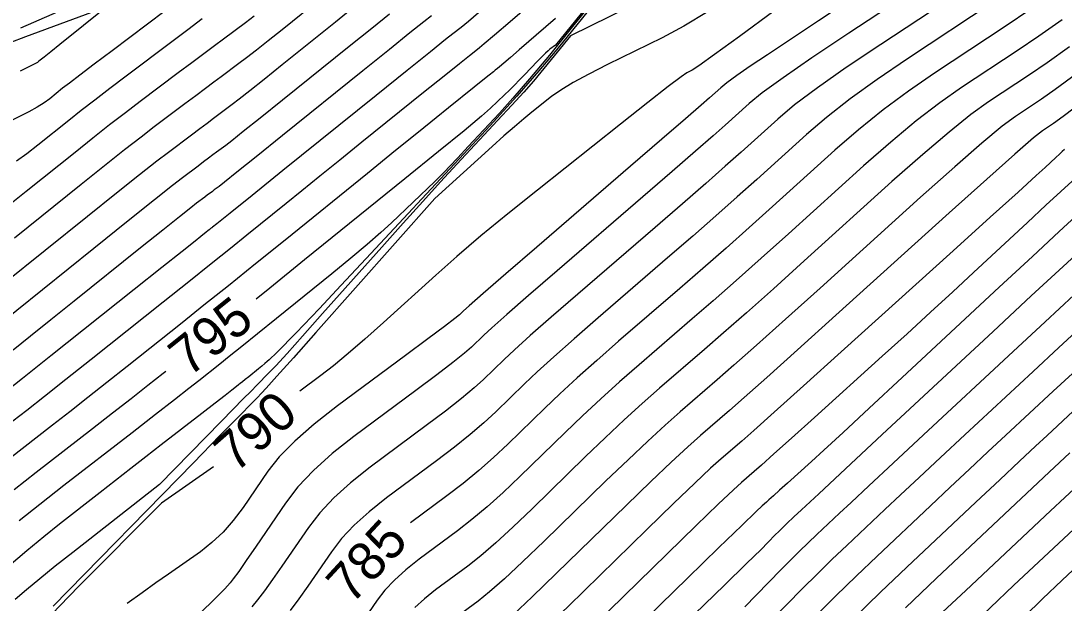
# Model space of a CAD drawing. Extents: x 2079879 to 2092887, y 778083 to 784051.
# Drawn here: x 2084359.8 to 2084435.7, y 781096.1 to 781138.5 of the extents above; entities that cross this region are included whole.
import ezdxf

# ---------------------------------------------------------------- set-up
doc = ezdxf.new("R2010")
doc.units = 0
doc.layers.add('DT_X_Contour_Major', color=7, linetype='Continuous')
doc.layers.add('DT_X_Contour_Minor', color=7, linetype='Continuous')

msp = doc.modelspace()

# ---------------------------------------------------------------- linework, layer by layer
at = {"layer": 'DT_X_Contour_Major'}
for points in [[(2084407.524, 781147.596), (2084398.692, 781136.684), (2084398.271, 781136.383), (2084398.148, 781136.28), (2084397.959, 781136.1), (2084397.704, 781135.844), (2084397.383, 781135.512), (2084396.439, 781134.523), (2084396.082, 781134.153), (2084395.72, 781133.787), (2084395.352, 781133.424), (2084394.978, 781133.065), (2084393.973, 781132.109), (2084393.302, 781131.519), (2084392.04, 781130.466), (2084390.188, 781128.948), (2084387.747, 781126.968), (2084380.449, 781121.068), (2084377.926, 781119.029), (2084376.92, 781118.218)], [(2084370.308, 781139.179), (2084366.451, 781136.283), (2084365.142, 781135.298), (2084364.106, 781134.513), (2084363.344, 781133.93), (2084362.856, 781133.547), (2084361.919, 781132.794), (2084361.515, 781132.5), (2084361.008, 781132.184), (2084360.396, 781131.844), (2084359.681, 781131.482), (2084357.634, 781130.485), (2084356.741, 781129.967), (2084355.597, 781129.161), (2084354.202, 781128.067), (2084353.247, 781127.265)], [(2084386.613, 781138.939), (2084385.327, 781137.907), (2084383.687, 781136.588), (2084378.841, 781132.687), (2084377.22, 781131.383), (2084375.991, 781130.4), (2084375.155, 781129.736), (2084374.711, 781129.393), (2084374.051, 781128.902), (2084373.781, 781128.702), (2084373.467, 781128.467), (2084373.108, 781128.198), (2084372.704, 781127.895), (2084371.568, 781127.042), (2084370.845, 781126.481), (2084369.528, 781125.437), (2084367.618, 781123.91), (2084365.113, 781121.901), (2084357.641, 781115.898), (2084355.184, 781113.926), (2084353.573, 781112.636)], [(2084414.557, 781139.145), (2084412.07, 781137.326), (2084410.253, 781136.007), (2084409.104, 781135.186), (2084408.623, 781134.865), (2084408.233, 781134.673), (2084407.822, 781134.386), (2084406.881, 781133.668), (2084405.412, 781132.519), (2084403.413, 781130.94), (2084397.377, 781126.153), (2084395.218, 781124.421), (2084393.267, 781122.814), (2084391.526, 781121.331), (2084389.993, 781119.974), (2084386.184, 781116.521), (2084384.828, 781115.308), (2084383.614, 781114.261), (2084382.544, 781113.379), (2084381.618, 781112.661), (2084380.099, 781111.534)], [(2084433.261, 781139.295), (2084431.394, 781138.043), (2084426.258, 781134.651), (2084424.36, 781133.346), (2084422.52, 781131.976), (2084420.736, 781130.541), (2084419.01, 781129.04), (2084414.481, 781124.952), (2084412.786, 781123.43), (2084411.098, 781121.931), (2084409.416, 781120.455), (2084407.741, 781119.002), (2084403.283, 781115.158), (2084401.694, 781113.773), (2084400.27, 781112.503), (2084399.012, 781111.347), (2084397.919, 781110.304), (2084395.225, 781107.677), (2084394.191, 781106.704), (2084393.109, 781105.753), (2084391.979, 781104.827), (2084390.802, 781103.923), (2084388.157, 781101.959)], [(2084435.706, 781129.108), (2084435.542, 781128.957), (2084435.328, 781128.758), (2084435.062, 781128.512), (2084434.287, 781127.79), (2084433.651, 781127.209), (2084432.325, 781126.006), (2084430.308, 781124.183), (2084427.601, 781121.738), (2084419.463, 781114.39), (2084416.722, 781111.918), (2084414.603, 781110.014), (2084413.106, 781108.677), (2084412.232, 781107.908), (2084410.729, 781106.612), (2084409.969, 781105.926), (2084408.815, 781104.841), (2084407.268, 781103.356), (2084405.328, 781101.471), (2084399.628, 781095.913), (2084397.709, 781094.054), (2084396.816, 781093.203)], [(2084437.141, 781116.411), (2084435.28, 781114.697), (2084433.417, 781112.97), (2084428.449, 781108.346), (2084426.689, 781106.707), (2084425.134, 781105.256), (2084423.786, 781103.995), (2084422.643, 781102.922), (2084419.871, 781100.315), (2084418.818, 781099.313), (2084417.74, 781098.263), (2084416.636, 781097.164), (2084415.505, 781096.018), (2084412.457, 781092.896), (2084411.278, 781091.698), (2084410.029, 781090.445), (2084408.709, 781089.138), (2084407.317, 781087.777), (2084406.034, 781086.527)], [(2084370.36, 781112.971), (2084370.154, 781112.806), (2084369.058, 781111.938), (2084367.837, 781110.979), (2084366.491, 781109.928), (2084365.019, 781108.786), (2084360.929, 781105.619), (2084359.33, 781104.356)], [(2084373.825, 781106.031), (2084370.044, 781103.39), (2084364.036, 781097.358), (2084362.64, 781095.93), (2084361.029, 781094.228), (2084359.201, 781092.254)], [(2084437.075, 781102.155), (2084432.031, 781097.423), (2084430.302, 781095.791), (2084428.898, 781094.448), (2084427.82, 781093.391), (2084427.067, 781092.622), (2084425.493, 781090.954), (2084424.917, 781090.353), (2084424.371, 781089.801), (2084423.854, 781089.298), (2084423.366, 781088.845), (2084422.105, 781087.701), (2084421.464, 781087.091), (2084420.486, 781086.119), (2084419.172, 781084.785), (2084417.521, 781083.09), (2084415.383, 781080.885)]]:
    msp.add_lwpolyline(points, dxfattribs=at)
at = {"layer": 'DT_X_Contour_Minor'}
for points in [[(2084408.366, 781148.438), (2084399.937, 781138.033), (2084398.25, 781135.968), (2084396.801, 781134.233), (2084395.59, 781132.826), (2084394.617, 781131.748), (2084392.341, 781129.314), (2084391.581, 781128.501), (2084391.008, 781127.89), (2084390.621, 781127.48), (2084390.42, 781127.272), (2084389.92, 781126.767), (2084386.773, 781123.774), (2084385.995, 781123.061), (2084385.01, 781122.204), (2084383.819, 781121.205), (2084382.421, 781120.063), (2084378.416, 781116.825), (2084377.031, 781115.706), (2084375.88, 781114.778), (2084374.963, 781114.041), (2084374.279, 781113.495), (2084372.767, 781112.292), (2084372.038, 781111.717), (2084370.986, 781110.894), (2084369.61, 781109.824), (2084367.911, 781108.507), (2084362.948, 781104.664), (2084361.205, 781103.303), (2084359.699, 781102.104)], [(2084404.073, 781142.906), (2084398.783, 781136.377), (2084397.49, 781134.83), (2084395.878, 781132.988), (2084393.946, 781130.852), (2084391.695, 781128.42), (2084385.265, 781121.543), (2084383.118, 781119.249), (2084381.498, 781117.522), (2084380.405, 781116.364), (2084379.839, 781115.774), (2084378.427, 781114.348), (2084377.868, 781113.817), (2084377.729, 781113.69), (2084377.554, 781113.538), (2084377.343, 781113.36), (2084377.094, 781113.158), (2084376.383, 781112.582), (2084376.137, 781112.384), (2084375.933, 781112.219), (2084375.77, 781112.088), (2084375.648, 781111.991), (2084375.38, 781111.777), (2084375.153, 781111.6), (2084374.676, 781111.229), (2084373.948, 781110.664), (2084372.968, 781109.905), (2084370.021, 781107.623), (2084368.916, 781106.766), (2084367.809, 781105.906), (2084366.701, 781105.043), (2084365.593, 781104.176), (2084362.634, 781101.863), (2084361.485, 781100.945), (2084360.258, 781099.927), (2084358.952, 781098.809)], [(2084427.894, 781142.754), (2084420.01, 781137.546), (2084417.341, 781135.764), (2084415.247, 781134.321), (2084413.728, 781133.218), (2084412.784, 781132.455), (2084411.033, 781130.875), (2084410.167, 781130.104), (2084408.88, 781128.978), (2084407.173, 781127.496), (2084405.047, 781125.659), (2084398.815, 781120.286), (2084396.729, 781118.482), (2084395.143, 781117.1), (2084394.058, 781116.141), (2084393.474, 781115.604), (2084392.583, 781114.735), (2084392.08, 781114.293), (2084391.237, 781113.62), (2084390.057, 781112.714), (2084388.537, 781111.576), (2084384.033, 781108.232), (2084382.456, 781106.989), (2084381.101, 781105.767), (2084379.968, 781104.566), (2084379.059, 781103.387), (2084376.929, 781100.27), (2084376.212, 781099.226), (2084375.658, 781098.434), (2084375.267, 781097.892), (2084375.038, 781097.601), (2084374.647, 781097.159), (2084374.363, 781096.866), (2084373.807, 781096.319), (2084372.977, 781095.518)], [(2084406.892, 781140.865), (2084399.781, 781137.374), (2084397.63, 781134.72), (2084397.088, 781134.073), (2084396.382, 781133.271), (2084395.513, 781132.314), (2084394.482, 781131.2), (2084391.513, 781128.024), (2084390.337, 781126.755), (2084389.036, 781125.33), (2084387.61, 781123.749), (2084386.06, 781122.011), (2084381.758, 781117.169), (2084380.304, 781115.537), (2084379.17, 781114.276), (2084378.355, 781113.384), (2084377.86, 781112.862), (2084376.965, 781111.962), (2084376.552, 781111.543), (2084375.982, 781110.964), (2084375.256, 781110.224), (2084374.373, 781109.322), (2084369.89, 781104.737), (2084363.595, 781099.815), (2084362.322, 781098.809), (2084361.2, 781097.901), (2084360.229, 781097.091), (2084359.409, 781096.379)], [(2084429.636, 781141.564), (2084422.339, 781136.744), (2084419.82, 781135.049), (2084417.733, 781133.58), (2084416.08, 781132.336), (2084414.859, 781131.317), (2084412.183, 781128.9), (2084411.04, 781127.879), (2084409.619, 781126.629), (2084407.921, 781125.149), (2084405.945, 781123.44), (2084400.305, 781118.576), (2084398.384, 781116.912), (2084396.852, 781115.568), (2084395.71, 781114.543), (2084394.956, 781113.837), (2084393.464, 781112.383), (2084392.783, 781111.763), (2084391.861, 781110.998), (2084390.698, 781110.085), (2084389.292, 781109.025), (2084385.222, 781106.003), (2084383.796, 781104.88), (2084382.572, 781103.775), (2084381.549, 781102.69), (2084380.726, 781101.624), (2084378.802, 781098.808), (2084378.124, 781097.831), (2084377.533, 781097.013), (2084377.029, 781096.354), (2084376.612, 781095.853)], [(2084381.713, 781140.141), (2084378.817, 781137.81), (2084377.807, 781137), (2084376.946, 781136.319), (2084376.236, 781135.766), (2084375.676, 781135.342), (2084374.383, 781134.381), (2084373.855, 781133.988), (2084373.239, 781133.528), (2084372.536, 781133.002), (2084371.746, 781132.409), (2084369.521, 781130.739), (2084368.564, 781130.008), (2084367.359, 781129.068), (2084365.908, 781127.918), (2084364.21, 781126.559), (2084359.352, 781122.656)], [(2084393.463, 781139.354), (2084392.359, 781138.412), (2084391.836, 781137.978), (2084391.22, 781137.499), (2084390.699, 781137.085), (2084389.599, 781136.203), (2084387.919, 781134.853), (2084385.66, 781133.035), (2084378.864, 781127.563), (2084376.633, 781125.767), (2084375.036, 781124.481), (2084374.074, 781123.707), (2084373.746, 781123.444), (2084373.718, 781123.423), (2084373.707, 781123.415), (2084373.694, 781123.405), (2084373.679, 781123.394), (2084373.662, 781123.381), (2084373.615, 781123.346), (2084373.581, 781123.32), (2084373.516, 781123.268), (2084373.419, 781123.19), (2084373.29, 781123.086), (2084372.904, 781122.776), (2084372.493, 781122.448), (2084371.549, 781121.697), (2084370.073, 781120.522), (2084368.065, 781118.924), (2084361.999, 781114.099), (2084359.94, 781112.462), (2084358.311, 781111.171)], [(2084384.031, 781139.435), (2084382.7, 781138.365), (2084378.829, 781135.248), (2084377.513, 781134.192), (2084376.469, 781133.359), (2084375.696, 781132.751), (2084375.194, 781132.367), (2084374.217, 781131.642), (2084373.818, 781131.345), (2084373.353, 781130.997), (2084372.822, 781130.6), (2084372.225, 781130.152), (2084370.545, 781128.891), (2084369.705, 781128.244), (2084368.444, 781127.252), (2084366.763, 781125.914), (2084364.661, 781124.23), (2084358.497, 781119.277)], [(2084359.05, 781136.889), (2084360.168, 781137.303), (2084366.091, 781139.496), (2084362.64, 781136.725), (2084361.989, 781136.202), (2084361.516, 781135.822), (2084361.22, 781135.585), (2084361.102, 781135.49), (2084361.024, 781135.427), (2084360.923, 781135.37), (2084360.68, 781135.246), (2084360.295, 781135.054), (2084359.767, 781134.796)], [(2084396.938, 781139.724), (2084395.394, 781138.391), (2084394.249, 781137.406), (2084393.503, 781136.77), (2084393.158, 781136.482), (2084392.768, 781136.179), (2084392.43, 781135.91), (2084391.706, 781135.33), (2084390.599, 781134.44), (2084389.106, 781133.239), (2084384.614, 781129.622), (2084383.006, 781128.326), (2084381.551, 781127.154), (2084380.25, 781126.104), (2084379.102, 781125.177), (2084376.245, 781122.867), (2084375.062, 781121.913), (2084373.655, 781120.786), (2084372.025, 781119.483), (2084370.171, 781118.006), (2084364.928, 781113.835), (2084363.098, 781112.382), (2084361.539, 781111.149), (2084360.252, 781110.137), (2084359.237, 781109.345)], [(2084363.406, 781139.502), (2084359.802, 781137.917)], [(2084419.246, 781139.397), (2084417.828, 781138.446), (2084414.114, 781135.992), (2084412.856, 781135.153), (2084411.87, 781134.473), (2084411.154, 781133.953), (2084410.709, 781133.594), (2084409.884, 781132.849), (2084409.294, 781132.329), (2084408.141, 781131.327), (2084406.426, 781129.843), (2084404.149, 781127.878), (2084397.326, 781121.995), (2084395.074, 781120.051), (2084393.434, 781118.633), (2084392.407, 781117.739), (2084391.992, 781117.371), (2084391.702, 781117.088), (2084391.376, 781116.823), (2084390.614, 781116.242), (2084389.416, 781115.343), (2084387.782, 781114.127), (2084382.845, 781110.461), (2084381.14, 781109.134), (2084379.728, 781107.902), (2084378.609, 781106.765), (2084377.783, 781105.723), (2084375.971, 781103.07), (2084375.267, 781102.124), (2084374.516, 781101.274), (2084373.716, 781100.52), (2084372.869, 781099.863), (2084370.546, 781098.24), (2084369.633, 781097.597), (2084368.638, 781096.884), (2084367.559, 781096.101)], [(2084430.515, 781139.803), (2084424.299, 781135.697), (2084422.09, 781134.198), (2084420.127, 781132.778), (2084418.408, 781131.438), (2084416.934, 781130.179), (2084413.332, 781126.926), (2084411.913, 781125.655), (2084410.359, 781124.28), (2084408.669, 781122.802), (2084406.843, 781121.221), (2084401.794, 781116.867), (2084400.039, 781115.343), (2084398.561, 781114.035), (2084397.361, 781112.945), (2084396.437, 781112.071), (2084394.344, 781110.03), (2084393.487, 781109.234), (2084392.485, 781108.375), (2084391.338, 781107.456), (2084390.047, 781106.474), (2084386.411, 781103.774), (2084385.137, 781102.771), (2084384.043, 781101.784), (2084383.129, 781100.814), (2084382.394, 781099.862), (2084380.675, 781097.345), (2084380.036, 781096.435), (2084379.408, 781095.592)], [(2084398.689, 781138.623), (2084398, 781138.018), (2084396.058, 781136.339), (2084395.413, 781135.782), (2084394.934, 781135.371), (2084394.623, 781135.105), (2084394.479, 781134.985), (2084394.316, 781134.858), (2084394.175, 781134.746), (2084393.873, 781134.504), (2084393.41, 781134.132), (2084392.787, 781133.631), (2084390.911, 781132.12), (2084390.015, 781131.398), (2084388.733, 781130.363), (2084387.067, 781129.017), (2084385.015, 781127.358), (2084379.029, 781122.518), (2084376.877, 781120.781), (2084374.912, 781119.2), (2084373.133, 781117.773), (2084371.54, 781116.502), (2084367.541, 781113.321), (2084366.078, 781112.16), (2084364.688, 781111.064), (2084363.371, 781110.032), (2084362.128, 781109.066), (2084358.91, 781106.574)], [(2084376.777, 781138.781), (2084376.159, 781138.316), (2084374.55, 781137.121), (2084373.892, 781136.631), (2084373.125, 781136.059), (2084372.25, 781135.404), (2084371.266, 781134.666), (2084368.498, 781132.587), (2084367.423, 781131.771), (2084366.275, 781130.883), (2084365.053, 781129.922), (2084363.758, 781128.888), (2084360.208, 781126.036), (2084358.983, 781125.07)], [(2084389.672, 781138.819), (2084389.122, 781138.384), (2084388.106, 781137.571), (2084386.623, 781136.38), (2084384.673, 781134.812), (2084378.852, 781130.125), (2084376.926, 781128.575), (2084375.513, 781127.441), (2084374.614, 781126.722), (2084374.229, 781126.418), (2084373.885, 781126.163), (2084373.744, 781126.058), (2084373.58, 781125.936), (2084373.393, 781125.796), (2084373.183, 781125.638), (2084372.592, 781125.194), (2084372.171, 781124.867), (2084371.354, 781124.217), (2084370.14, 781123.246), (2084368.529, 781121.953), (2084363.704, 781118.077), (2084362.005, 781116.713), (2084360.526, 781115.527), (2084359.268, 781114.521)], [(2084373.011, 781138.59), (2084371.964, 781137.806), (2084370.787, 781136.922), (2084367.474, 781134.435), (2084366.282, 781133.535), (2084365.19, 781132.698), (2084364.199, 781131.926), (2084363.307, 781131.218), (2084361.063, 781129.415), (2084360.249, 781128.785), (2084359.489, 781128.249)], [(2084409.792, 781139.133), (2084408.03, 781138.066), (2084406.449, 781137.223), (2084402.478, 781135.273), (2084401.107, 781134.58), (2084399.972, 781133.962), (2084399.075, 781133.419), (2084398.414, 781132.951), (2084396.969, 781131.805), (2084396.382, 781131.327), (2084395.708, 781130.754), (2084394.946, 781130.086), (2084394.095, 781129.323), (2084389.92, 781125.538), (2084381.275, 781115.807), (2084379.638, 781113.966), (2084378.434, 781112.616), (2084377.661, 781111.756), (2084377.321, 781111.386), (2084376.99, 781111.053), (2084376.608, 781110.664), (2084375.71, 781109.747), (2084374.297, 781108.303), (2084372.369, 781106.332), (2084362.167, 781095.899)], [(2084435.534, 781138.537), (2084433.848, 781137.348), (2084432.272, 781136.283), (2084428.217, 781133.604), (2084426.631, 781132.494), (2084424.913, 781131.174), (2084423.065, 781129.643), (2084421.085, 781127.902), (2084415.63, 781122.978), (2084413.659, 781121.205), (2084411.837, 781119.582), (2084410.164, 781118.108), (2084408.639, 781116.783), (2084404.772, 781113.449), (2084403.349, 781112.204), (2084401.979, 781110.97), (2084400.663, 781109.748), (2084399.401, 781108.538), (2084396.105, 781105.324), (2084394.894, 781104.174), (2084393.733, 781103.131), (2084392.62, 781102.198), (2084391.557, 781101.372), (2084388.788, 781099.317), (2084387.818, 781098.552), (2084386.985, 781097.801), (2084386.289, 781097.063), (2084385.73, 781096.337), (2084384.42, 781094.421)], [(2084436.056, 781136.567), (2084434.435, 781135.402), (2084433.151, 781134.522), (2084430.176, 781132.557), (2084428.901, 781131.643), (2084427.307, 781130.372), (2084425.393, 781128.746), (2084423.16, 781126.764), (2084416.78, 781121.003), (2084414.532, 781118.981), (2084412.576, 781117.233), (2084410.911, 781115.761), (2084409.537, 781114.564), (2084406.262, 781111.739), (2084405.004, 781110.634), (2084403.688, 781109.438), (2084402.315, 781108.15), (2084400.882, 781106.771), (2084396.986, 781102.972), (2084395.598, 781101.644), (2084394.356, 781100.509), (2084393.261, 781099.569), (2084392.312, 781098.821), (2084389.977, 781097.088), (2084389.159, 781096.443), (2084388.456, 781095.809)], [(2084436.578, 781134.597), (2084435.022, 781133.455), (2084434.03, 781132.762), (2084432.136, 781131.511), (2084431.172, 781130.791), (2084429.7, 781129.57), (2084427.721, 781127.848), (2084425.235, 781125.625), (2084417.929, 781119.029), (2084415.406, 781116.756), (2084413.316, 781114.884), (2084411.659, 781113.414), (2084410.436, 781112.345), (2084407.751, 781110.03), (2084406.659, 781109.065), (2084405.397, 781107.906), (2084403.966, 781106.552), (2084402.364, 781105.005), (2084397.867, 781100.619), (2084396.302, 781099.114), (2084394.98, 781097.887), (2084393.902, 781096.939), (2084393.067, 781096.271), (2084391.166, 781094.859)], [(2084437.099, 781132.627), (2084435.609, 781131.509), (2084434.908, 781131.002), (2084434.095, 781130.464), (2084433.442, 781129.939), (2084432.094, 781128.768), (2084430.05, 781126.951), (2084427.31, 781124.487), (2084419.078, 781117.055), (2084416.279, 781114.531), (2084414.055, 781112.536), (2084412.407, 781111.067), (2084411.334, 781110.126), (2084409.24, 781108.321), (2084408.314, 781107.496), (2084407.106, 781106.373), (2084405.617, 781104.954), (2084403.846, 781103.238), (2084398.747, 781098.266), (2084397.005, 781096.584), (2084395.604, 781095.265)], [(2084436.257, 781126.808), (2084435.431, 781126.046), (2084434.347, 781125.043), (2084433.008, 781123.797), (2084429.092, 781120.154), (2084427.576, 781118.749), (2084425.964, 781117.268), (2084424.257, 781115.711), (2084422.453, 781114.078), (2084417.516, 781109.621), (2084415.854, 781108.122), (2084414.568, 781106.966), (2084413.661, 781106.155), (2084413.13, 781105.689), (2084412.219, 781104.903), (2084411.624, 781104.357), (2084410.524, 781103.308), (2084408.92, 781101.758), (2084406.809, 781099.705), (2084400.508, 781093.561)], [(2084436.808, 781124.509), (2084435.319, 781123.135), (2084433.367, 781121.327), (2084430.953, 781119.083), (2084423.898, 781112.517), (2084421.502, 781110.29), (2084419.604, 781108.531), (2084418.205, 781107.24), (2084417.305, 781106.419), (2084415.57, 781104.852), (2084414.986, 781104.325), (2084414.534, 781103.919), (2084414.215, 781103.634), (2084414.028, 781103.47), (2084413.708, 781103.193), (2084413.279, 781102.787), (2084412.233, 781101.776), (2084410.571, 781100.16), (2084408.291, 781097.938), (2084401.389, 781091.208)], [(2084437.459, 781122.302), (2084435.609, 781120.599), (2084433.291, 781118.453), (2084430.506, 781115.865), (2084422.455, 781108.373), (2084419.789, 781105.891), (2084417.83, 781104.067), (2084416.576, 781102.9), (2084416.03, 781102.389), (2084415.513, 781101.903), (2084415.317, 781101.717), (2084415.116, 781101.521), (2084414.91, 781101.316), (2084414.7, 781101.103), (2084414.132, 781100.521), (2084413.639, 781100.032), (2084412.588, 781099.002), (2084410.978, 781097.43), (2084408.809, 781095.317)], [(2084436.375, 781118.505), (2084434.286, 781116.575), (2084431.962, 781114.417), (2084425.452, 781108.359), (2084423.239, 781106.299), (2084421.482, 781104.662), (2084420.181, 781103.447), (2084419.336, 781102.656), (2084417.692, 781101.109), (2084417.068, 781100.515), (2084416.428, 781099.892), (2084415.773, 781099.24), (2084415.102, 781098.56), (2084413.294, 781096.708), (2084412.459, 781095.865)], [(2084436.274, 781112.819), (2084434.873, 781111.522), (2084431.446, 781108.333), (2084430.138, 781107.114), (2084428.787, 781105.851), (2084427.391, 781104.542), (2084425.95, 781103.189), (2084422.05, 781099.521), (2084420.569, 781098.111), (2084419.052, 781096.634), (2084417.498, 781095.088)], [(2084436.329, 781110.075), (2084434.443, 781108.319), (2084433.588, 781107.522), (2084432.439, 781106.445), (2084430.995, 781105.09), (2084429.257, 781103.456), (2084424.229, 781098.726), (2084422.32, 781096.909), (2084420.364, 781095.004)], [(2084436.091, 781107.04), (2084434.6, 781105.637), (2084432.564, 781103.722), (2084426.408, 781097.932), (2084424.15, 781095.788)], [(2084436.77, 781104.783), (2084434.691, 781102.833), (2084428.531, 781097.053), (2084426.495, 781095.141)], [(2084439.459, 781101.478), (2084435.53, 781097.792), (2084434.109, 781096.442), (2084432.791, 781095.158)]]:
    msp.add_lwpolyline(points, dxfattribs=at)

# ---------------------------------------------------------------- texts
at = {"layer": 'DT_X_Contour_Major'}
for s, rotation, p in [('795', 38.65999, (2084372.033, 781112.504)), ('790', 41.25388, (2084375.42, 781105.522)), ('785', 47.34256, (2084383.865, 781095.95))]:
    msp.add_text(s, height=2.8, rotation=rotation, dxfattribs=at).set_placement(p)

doc.saveas('drawing.dxf')
